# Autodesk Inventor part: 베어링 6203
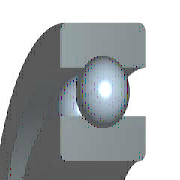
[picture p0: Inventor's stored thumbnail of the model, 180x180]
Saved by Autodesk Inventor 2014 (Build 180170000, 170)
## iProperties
IsCustomPart: 1
Created: 2015-09
Part Number: 베어링 6203
Material: 강철, 연강
Description: 깊은 그루브 볼 베어링
Document SubType Name: Modeling
Standard: KS B 2023
Standards Organization: KS
Language: ko-KR
Size Designation: 6203 - 17 x 40 x 12
Categories: <MemberInstance><Categories><Category DisplayName="샤프트 부품" InternalName="7f7aeb1f-a693-4053-b835-cee3144e0d98" Mnemonic="SHFT"><Category DisplayName="베어링" Inter
Density: 7.86 g/cm^3
Mass: 64.9809 g
Surface Area: 64.3582 cm^2
Volume: 8.26729 cm^3
Appearance: Yellow
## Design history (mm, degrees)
sketch "스케치" dims "d0" = 5.98 (= -0.26 x WD + 0.26 x BD)
  geometry: L1 (3.01, 14.25)-(8.99, 14.25); L2 (6, 14.25)-(6, 11.26); L3 (6, 14.25)-(6, 17.24); L4 (3.778, 12.249)-(0, 12.249); L5 (0, 8.5)-(12, 8.5); L6 (3.778, 16.251)-(0, 16.251); L7 (0, 20)-(12, 20); L8 (12, 8.5)-(12, 12.249); L9 (8.222, 12.249)-(12, 12.249); L10 (8.222, 16.251)-(12, 16.251); L11 (12, 20)-(12, 16.251); L12 (-1.4, 0)-(8.4, 0) reference; L13 (0, -0.3)-(0, 5.3) reference
  constraints: 22 end point, 4 point on line, 2 collinear, 2 perpendicular, 2 symmetric about line, 1 midpoint, 1 parallel, 14 other
  dimensions: "d9" = 17 diameter of L5 L12 (= WD); "d11" = 40 diameter of L7 L12 (= BD); "d12" = 12 distance between parallel lines of L8 L13 (= KB); "d13" = 24.498 diameter of L9 L12 (= 0.326 x BD + 0.674 x WD)
revolve "본체" stored, may be unused: angle "d6" = 90 deg
revolve "볼" stored, may be unused: angle "d7" = 90 deg
pattern_circular "IDS_ARRAYBALL[SIMPL:T]" dims angle "d3" = 360 deg
body "Solid1"
fillet "모깎기1" dims "d1" = 0.6 (= KRS)
other parameters: "WD" = 17 [user parameter; used in 5 equation terms], "BD" = 40 [user parameter; used in 5 equation terms], "KB" = 12 [user parameter; used in 1 equation term], "KRS" = 0.6 [user parameter; used in 1 equation term], "d4" = 0, "d5" = 0, "d8" = 0, "d14" = 0, "d15" = 0, "BBA" = 0 [user parameter], "BC0" = 4750000 [user parameter], "BC" = 9560000 [user parameter], "WR" = 8.5 (= 0.5 x WD) [user parameter]
